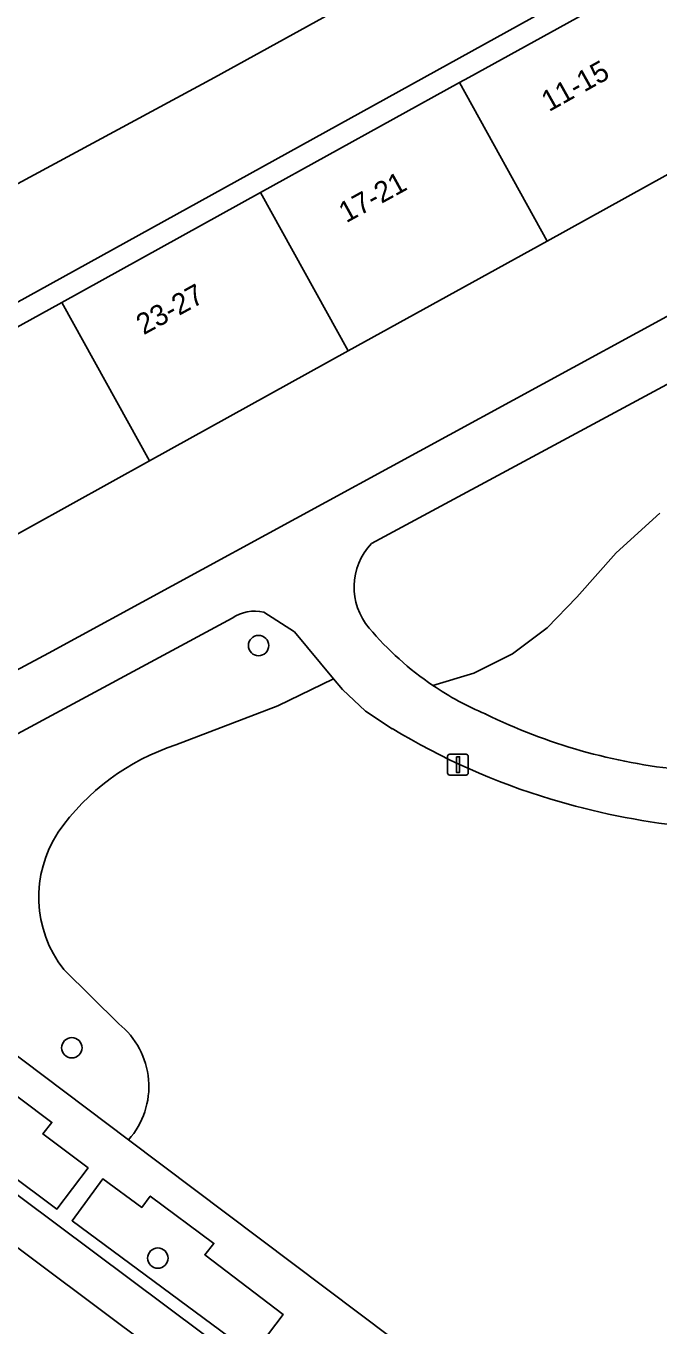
# Model space of a CAD drawing. Extents: x 159888 to 160761, y 384031 to 384750.
# Drawn here: x 160156.3 to 160186.6, y 384440.1 to 384502.5 of the extents above; entities that cross this region are included whole.
import ezdxf

# ---------------------------------------------------------------- set-up
doc = ezdxf.new("R2010")
doc.units = 0
for name, color, linetype in [('IMGEO_Boom', 7, 'Continuous'), ('IMGEO_Erf', 7, 'Continuous'), ('IMGEO_Groenvoorziening', 7, 'Continuous'), ('IMGEO_Lichtmast', 7, 'Continuous'), ('IMGEO_Pand', 7, 'Continuous'), ('IMGEO_Pand_nummerreeks', 7, 'Continuous'), ('IMGEO_Parkeervlak_open', 7, 'Continuous'), ('IMGEO_Rijbaan_lokaal_open', 7, 'Continuous'), ('IMGEO_Voetpad_gesloten', 7, 'Continuous'), ('IMGEO_Voetpad_open', 7, 'Continuous')]:
    doc.layers.add(name, color=color, linetype=linetype)

msp = doc.modelspace()

# ---------------------------------------------------------------- linework, layer by layer
at = {"layer": 'IMGEO_Boom'}
for centre in [(160167.423, 384472.713), (160158.464, 384453.4), (160162.589, 384443.3)]:
    msp.add_circle(centre, 0.489, dxfattribs=at)
at = {"layer": 'IMGEO_Erf'}
msp.add_lwpolyline([(160190.804, 384497.414), (160181.266, 384492.138), (160171.728, 384486.861), (160162.191, 384481.585), (160152.653, 384476.308), (160143.115, 384471.032), (160140.123, 384476.439), (160138.035, 384475.294), (160136.739, 384477.742), (160134.442, 384476.461), (160141.469, 384463.844), (160157.338, 384472.343), (160192.947, 384491.75)], dxfattribs=at)
at = {"layer": 'IMGEO_Groenvoorziening'}
for points in [[(160192.036, 384487.95), (160172.842, 384477.61)], [(160175.786, 384470.797), (160177.747, 384471.387), (160179.606, 384472.319), (160181.275, 384473.559), (160182.685, 384475.045), (160184.575, 384477.169), (160186.682, 384479.078)], [(160163.459, 384467.947), (160168.345, 384469.821), (160171.016, 384471.121), (160169.14, 384473.374), (160167.668, 384474.325)], [(160166.157, 384474.038), (160143.881, 384462.027), (160161.19, 384448.984)], [(160173.836, 384468.724), (160172.56, 384469.565), (160171.443, 384470.608), (160171.016, 384471.121), (160168.345, 384469.821), (160163.459, 384467.947)], [(160160.714, 384454.548), (160158.072, 384457.154)], [(160158.072, 384457.154), (160160.714, 384454.548)], [(160161.19, 384448.984), (160195.888, 384422.845), (160199.296, 384428.481), (160194.719, 384432.353)]]:
    msp.add_lwpolyline(points, dxfattribs=at)
for points in [[(160148.26, 384452.746), (160157.75, 384445.654), (160159.241, 384447.631), (160157.076, 384449.268), (160157.505, 384449.816), (160154.455, 384452.108), (160154.031, 384451.554), (160149.771, 384454.734)], [(160167.149, 384438.68), (160168.598, 384440.6), (160164.837, 384443.461), (160165.284, 384444.005), (160162.222, 384446.276), (160161.815, 384445.732), (160159.949, 384447.1), (160158.477, 384445.093)]]:
    msp.add_lwpolyline(points, close=True, dxfattribs=at)
for centre, radius, start, end in [((160175.043, 384475.519), 3.036, 136.46229, 220.34681), ((160167.246, 384472.424), 1.947, 77.49478, 124.01457), ((160184.148, 384483.146), 14.913, 220.03238, 235.89593), ((160191.1, 384497.271), 33.361, 238.83586, 253.1791), ((160166.91, 384457.399), 11.099, 108.11758, 145.03524), ((160166.91, 384457.399), 11.099, 108.11758, 145.03524), ((160191.951, 384500.415), 36.617, 253.32873, 263.54475), ((160162.55, 384460.636), 5.672, 146.59079, 217.86571), ((160162.55, 384460.636), 5.672, 146.59079, 217.86571), ((160158.305, 384451.54), 3.854, 318.46789, 51.3116), ((160158.305, 384451.54), 3.854, 318.46789, 51.3116)]:
    msp.add_arc(centre, radius, start, end, dxfattribs=at)
at = {"layer": 'IMGEO_Lichtmast'}
for p, q in [((160176.593, 384467.499), (160177.383, 384467.499)), ((160177.383, 384467.499), (160176.593, 384467.499)), ((160176.493, 384466.599), (160176.493, 384467.399)), ((160176.493, 384467.399), (160176.493, 384466.599)), ((160177.483, 384467.399), (160177.483, 384466.599)), ((160177.483, 384466.599), (160177.483, 384467.399)), ((160177.383, 384466.499), (160176.593, 384466.499)), ((160176.593, 384466.499), (160177.383, 384466.499))]:
    msp.add_line(p, q, dxfattribs=at)
msp.add_lwpolyline([(160176.913, 384467.374), (160177.063, 384467.374), (160177.063, 384466.624), (160176.913, 384466.624), (160176.913, 384467.374)], dxfattribs=at)
for centre, start, end in [((160176.593, 384467.399), 90, 180), ((160176.593, 384467.399), 90, 180), ((160177.383, 384467.399), 0, 90), ((160177.383, 384467.399), 360, 90), ((160176.593, 384466.599), 180, 270), ((160176.593, 384466.599), 180, 270), ((160177.383, 384466.599), 270, 0), ((160177.383, 384466.599), 270, 0)]:
    msp.add_arc(centre, 0.1, start, end, dxfattribs=at)
at = {"layer": 'IMGEO_Pand'}
for points in [[(160181.266, 384492.138), (160190.804, 384497.414), (160186.593, 384505.023), (160177.514, 384500), (160177.056, 384499.746)], [(160181.266, 384492.138), (160177.056, 384499.746), (160167.518, 384494.47), (160171.728, 384486.861)], [(160162.191, 384481.585), (160171.728, 384486.861), (160167.518, 384494.47), (160157.98, 384489.193)], [(160162.191, 384481.585), (160157.98, 384489.193), (160148.443, 384483.917), (160152.653, 384476.308)]]:
    msp.add_lwpolyline(points, close=True, dxfattribs=at)
at = {"layer": 'IMGEO_Parkeervlak_open'}
for points in [[(160125.926, 384466.149), (160126.25, 384465.909), (160132.389, 384461.371), (160181.504, 384424.593), (160191.755, 384416.654), (160197.083, 384412.292)], [(160195.645, 384416.095), (160192.948, 384418.258), (160182.773, 384426.163), (160175.222, 384431.836), (160129.823, 384465.807)]]:
    msp.add_lwpolyline(points, dxfattribs=at)
at = {"layer": 'IMGEO_Rijbaan_lokaal_open'}
for points in [[(160165.309, 384500), (160173.174, 384504.351), (160169.437, 384511.163), (160169.305, 384511.405), (160160.869, 384506.792), (160155.019, 384503.618), (160154.776, 384503.572), (160154.318, 384503.528), (160153.859, 384503.525), (160153.4, 384503.563), (160152.947, 384503.642), (160152.503, 384503.761), (160152.071, 384503.919), (160151.655, 384504.115), (160151.259, 384504.348), (160150.884, 384504.615), (160150.535, 384504.914), (160150.214, 384505.243), (160149.924, 384505.6), (160149.919, 384505.608), (160144.775, 384502.674), (160144.978, 384502.349)], [(160129.945, 384480.77), (160132.921, 384482.467), (160136.525, 384484.446), (160165.309, 384500)]]:
    msp.add_lwpolyline(points, dxfattribs=at)
msp.add_lwpolyline([(160132.389, 384461.371), (160126.25, 384465.909), (160123.3, 384461.916), (160126.77, 384459.353), (160146.048, 384444.942), (160155.276, 384438.063), (160172.683, 384425.02), (160178.248, 384420.845), (160183.142, 384417.08), (160187.785, 384413.501), (160192.098, 384409.987), (160194.701, 384407.79), (160197.493, 384411.067), (160197.918, 384411.586), (160197.083, 384412.292), (160191.755, 384416.654), (160181.504, 384424.593)], close=True, dxfattribs=at)
at = {"layer": 'IMGEO_Voetpad_gesloten'}
for points in [[(160194.145, 384491.56), (160192.947, 384491.75), (160157.338, 384472.343), (160141.469, 384463.844), (160143.881, 384462.027), (160166.157, 384474.038)], [(160172.842, 384477.61), (160192.036, 384487.95)], [(160186.682, 384479.078), (160184.575, 384477.169), (160182.685, 384475.045), (160181.275, 384473.559), (160179.606, 384472.319), (160177.747, 384471.387), (160175.786, 384470.797)], [(160167.668, 384474.325), (160169.14, 384473.374), (160171.016, 384471.121), (160171.443, 384470.608), (160172.56, 384469.565), (160173.836, 384468.724)]]:
    msp.add_lwpolyline(points, dxfattribs=at)
for centre, radius, start, end in [((160175.043, 384475.519), 3.036, 136.46229, 220.34681), ((160167.246, 384472.424), 1.947, 77.49478, 124.01457), ((160184.148, 384483.146), 14.913, 220.03238, 235.89593), ((160184.089, 384483.069), 14.817, 235.92039, 247.01197), ((160184.089, 384483.069), 14.817, 235.92039, 247.01197), ((160190.347, 384493.923), 27.295, 243.81426, 264.50687), ((160190.347, 384493.923), 27.295, 243.81426, 264.50687), ((160191.1, 384497.271), 33.361, 238.83586, 253.1791), ((160191.951, 384500.415), 36.617, 253.32873, 263.54475)]:
    msp.add_arc(centre, radius, start, end, dxfattribs=at)
at = {"layer": 'IMGEO_Voetpad_open'}
for points in [[(160175.365, 384500), (160196.41, 384511.643), (160195.384, 384516.714), (160194.348, 384516.163), (160189.233, 384513.236), (160184.709, 384510.733), (160173.174, 384504.351), (160165.309, 384500), (160136.525, 384484.446), (160132.921, 384482.467), (160129.945, 384480.77)], [(160196.41, 384511.643), (160175.365, 384500), (160138.4, 384479.55), (160138.905, 384478.64), (160148.443, 384483.917), (160157.98, 384489.193), (160167.518, 384494.47), (160177.056, 384499.746), (160177.514, 384500), (160186.593, 384505.023), (160196.075, 384510.23)], [(160122.036, 384477.509), (160128.738, 384473.281), (160134.442, 384476.461), (160136.739, 384477.742), (160138.035, 384475.294), (160140.123, 384476.439), (160138.905, 384478.64), (160138.4, 384479.55), (160175.365, 384500)], [(160207.322, 384411.973), (160208.023, 384412.632), (160208.513, 384413.041), (160208.929, 384413.426), (160211.321, 384415.455), (160214.643, 384418.258), (160214.173, 384418.814), (160207.34, 384413.056), (160197.935, 384421.095), (160195.888, 384422.845), (160161.19, 384448.984), (160143.881, 384462.027), (160141.469, 384463.844), (160128.738, 384473.281), (160122.036, 384477.509)], [(160129.823, 384465.807), (160175.222, 384431.836), (160182.773, 384426.163), (160192.948, 384418.258), (160195.645, 384416.095)]]:
    msp.add_lwpolyline(points, dxfattribs=at)
for points in [[(160149.771, 384454.734), (160154.031, 384451.554), (160154.455, 384452.108), (160157.505, 384449.816), (160157.076, 384449.268), (160159.241, 384447.631), (160157.75, 384445.654), (160148.26, 384452.746)], [(160159.949, 384447.1), (160161.815, 384445.732), (160162.222, 384446.276), (160165.284, 384444.005), (160164.837, 384443.461), (160168.598, 384440.6), (160167.149, 384438.68), (160158.477, 384445.093)]]:
    msp.add_lwpolyline(points, close=True, dxfattribs=at)

# ---------------------------------------------------------------- texts
at = {"layer": 'IMGEO_Pand_nummerreeks'}
for s, rotation, p in [('11-15', 29.23282, (160181.356, 384498.326)), ('17-21', 28.83097, (160171.626, 384492.989)), ('23-27', 28.7398, (160161.907, 384487.61))]:
    msp.add_text(s, height=1, rotation=rotation, dxfattribs=at).set_placement(p)

doc.saveas('drawing.dxf')
